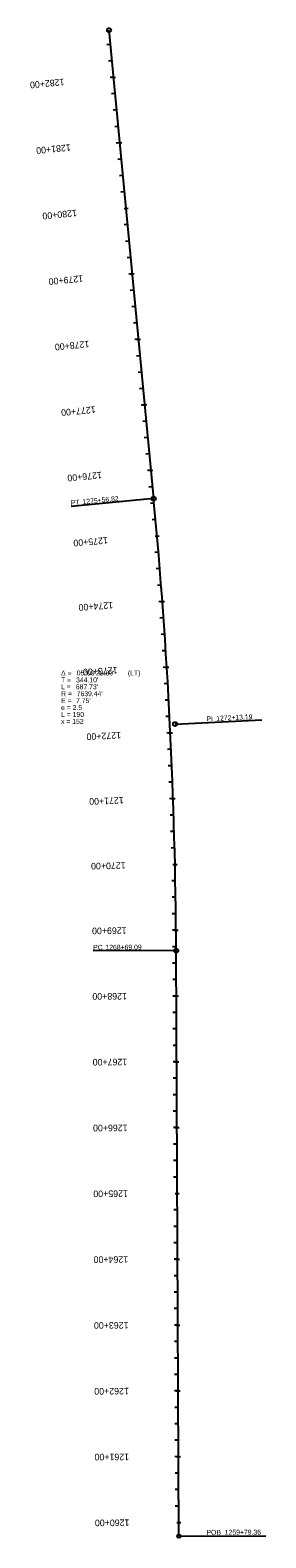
# Model space of a CAD drawing. Extents: x 19548215 to 19548727, y 7547983 to 7562114.
# Drawn here: x 19548369 to 19548727, y 7547983 to 7550274 of the extents above; entities that cross this region are included whole.
import ezdxf

# ---------------------------------------------------------------- set-up
doc = ezdxf.new("R2010")
doc.units = 0
for name, color, linetype in [('Contours Major', 7, 'Continuous'), ('Contours Minor', 7, 'Continuous'), ('Default', 7, 'Continuous'), ('TextAlignment', 7, 'Continuous'), ('TextAlignmentSml', 7, 'Continuous')]:
    doc.layers.add(name, color=color, linetype=linetype)

msp = doc.modelspace()

# ---------------------------------------------------------------- linework, layer by layer
at = {"layer": 'Contours Major'}
for p, q in [((19548495.4, 7550202), (19548490, 7550201.5)), ((19548504.9, 7550102.4), (19548499.5, 7550101.9)), ((19548511.3, 7550002.6), (19548517.4, 7550003.2)), ((19548523.8, 7549903.3), (19548518.4, 7549902.8)), ((19548533.3, 7549803.8), (19548527.8, 7549803.3)), ((19548542.7, 7549704.2), (19548537.3, 7549703.7)), ((19548552.2, 7549604.7), (19548546.8, 7549604.2)), ((19548558.4, 7549504.8), (19548564.5, 7549505.4)), ((19548569.5, 7549405.4), (19548564.1, 7549405)), ((19548576.3, 7549305.7), (19548570.8, 7549305.3)), ((19548581.7, 7549205.8), (19548576.3, 7549205.5)), ((19548585.9, 7549105.9), (19548580.4, 7549105.7)), ((19548585.6, 7549005.9), (19548591.8, 7549006)), ((19548590.2, 7548905.9), (19548584.8, 7548905.9)), ((19548590.8, 7548805.9), (19548585.3, 7548805.9)), ((19548591.2, 7548705.9), (19548585.8, 7548705.9)), ((19548591.7, 7548605.9), (19548586.2, 7548605.9)), ((19548589.1, 7548505.9), (19548595.2, 7548506)), ((19548592.6, 7548405.9), (19548587.2, 7548405.9)), ((19548593.1, 7548305.9), (19548587.7, 7548305.9)), ((19548593.6, 7548205.9), (19548588.1, 7548205.9)), ((19548594.1, 7548106), (19548588.6, 7548105.9)), ((19548591.5, 7548005.9), (19548597.6, 7548006))]:
    msp.add_line(p, q, dxfattribs=at)
at = {"layer": 'Contours Minor'}
for p, q in [((19548556.3, 7549561.7), (19548488.6, 7550273.5)), ((19548594.6, 7547985.3), (19548590.4, 7548875))]:
    msp.add_line(p, q, dxfattribs=at)
msp.add_arc((19540951.1, 7548839.1), 7639.4, 0.26937, 5.42737, dxfattribs=at)
at = {"layer": 'Default'}
msp.add_line((19548556.3, 7549561.7), (19548488.6, 7550273.5), dxfattribs=at)
msp.add_arc((19540951.1, 7548839.1), 7639.4, 0.26937, 5.42737, dxfattribs=at)
at = {"layer": 'TextAlignment'}
for p, q in [((19548556.3, 7549561.7), (19548430.8, 7549549.8)), ((19548430.8, 7549549.8), (19548430.8, 7549549.8)), ((19548588.8, 7549219.1), (19548720.7, 7549225.7)), ((19548720.7, 7549225.7), (19548720.7, 7549225.7)), ((19548590.4, 7548875), (19548464.4, 7548874.4)), ((19548464.4, 7548874.4), (19548464.4, 7548874.4)), ((19548594.6, 7547985.3), (19548726.6, 7547985.9)), ((19548726.6, 7547985.9), (19548726.6, 7547985.9))]:
    msp.add_line(p, q, dxfattribs=at)
for centre, radius in [((19548488.6, 7550273.5), 3.12), ((19548556.3, 7549561.7), 3.12), ((19548588.8, 7549219.1), 3.12), ((19548590.4, 7548875), 3.12), ((19548594.6, 7547985.3), 2.67)]:
    msp.add_circle(centre, radius, dxfattribs=at)
at = {"layer": 'TextAlignmentSml'}
for p, q in [((19548490.7, 7550251.8), (19548485.3, 7550251.2)), ((19548493.1, 7550226.9), (19548487.6, 7550226.3)), ((19548492.4, 7550201.7), (19548498.5, 7550202.3)), ((19548497.8, 7550177.1), (19548492.4, 7550176.6)), ((19548500.2, 7550152.2), (19548494.7, 7550151.7)), ((19548502.5, 7550127.3), (19548497.1, 7550126.8)), ((19548501.9, 7550102.1), (19548507.9, 7550102.7)), ((19548507.3, 7550077.5), (19548501.8, 7550077)), ((19548509.6, 7550052.6), (19548504.2, 7550052.1)), ((19548512, 7550027.8), (19548506.6, 7550027.2)), ((19548511.3, 7550002.6), (19548517.4, 7550003.2)), ((19548516.7, 7549978), (19548511.3, 7549977.5)), ((19548519.1, 7549953.1), (19548513.7, 7549952.6)), ((19548521.5, 7549928.2), (19548516, 7549927.7)), ((19548520.8, 7549903), (19548526.9, 7549903.6)), ((19548526.2, 7549878.4), (19548520.7, 7549877.9)), ((19548528.5, 7549853.5), (19548523.1, 7549853)), ((19548530.9, 7549828.7), (19548525.5, 7549828.1)), ((19548530.2, 7549803.5), (19548536.3, 7549804.1)), ((19548535.6, 7549778.9), (19548530.2, 7549778.4)), ((19548538, 7549754), (19548532.6, 7549753.5)), ((19548540.4, 7549729.1), (19548534.9, 7549728.6)), ((19548539.7, 7549703.9), (19548545.8, 7549704.5)), ((19548545.1, 7549679.3), (19548539.7, 7549678.8)), ((19548547.5, 7549654.4), (19548542, 7549653.9)), ((19548549.8, 7549629.6), (19548544.4, 7549629)), ((19548549.1, 7549604.4), (19548555.2, 7549605)), ((19548554.6, 7549579.8), (19548549.1, 7549579.3)), ((19548556.9, 7549554.9), (19548551.5, 7549554.4)), ((19548559.2, 7549530), (19548553.8, 7549529.5)), ((19548558.4, 7549504.8), (19548564.5, 7549505.4)), ((19548563.6, 7549480.2), (19548558.1, 7549479.7)), ((19548565.6, 7549455.3), (19548560.2, 7549454.8)), ((19548567.6, 7549430.4), (19548562.2, 7549429.9)), ((19548566.5, 7549405.2), (19548572.6, 7549405.6)), ((19548571.3, 7549380.5), (19548565.9, 7549380.1)), ((19548573, 7549355.5), (19548567.6, 7549355.2)), ((19548574.7, 7549330.6), (19548569.2, 7549330.3)), ((19548573.2, 7549305.5), (19548579.3, 7549305.8)), ((19548577.7, 7549280.7), (19548572.3, 7549280.4)), ((19548579.2, 7549255.7), (19548573.7, 7549255.4)), ((19548580.5, 7549230.8), (19548575, 7549230.5)), ((19548578.7, 7549205.7), (19548584.8, 7549205.9)), ((19548582.9, 7549180.8), (19548577.4, 7549180.6)), ((19548584, 7549155.9), (19548578.5, 7549155.6)), ((19548584.9, 7549130.9), (19548579.5, 7549130.7)), ((19548582.8, 7549105.8), (19548588.9, 7549106)), ((19548586.7, 7549080.9), (19548581.2, 7549080.7)), ((19548587.4, 7549055.9), (19548582, 7549055.8)), ((19548588.1, 7549030.9), (19548582.7, 7549030.8)), ((19548585.6, 7549005.9), (19548591.8, 7549006)), ((19548589.2, 7548980.9), (19548583.7, 7548980.8)), ((19548589.6, 7548955.9), (19548584.2, 7548955.9)), ((19548590, 7548930.9), (19548584.5, 7548930.9)), ((19548587.2, 7548905.9), (19548593.3, 7548906)), ((19548590.4, 7548880.9), (19548584.9, 7548880.9)), ((19548590.5, 7548855.9), (19548585.1, 7548855.9)), ((19548590.6, 7548830.9), (19548585.2, 7548830.9)), ((19548587.7, 7548805.9), (19548593.8, 7548806)), ((19548590.9, 7548780.9), (19548585.4, 7548780.9)), ((19548591, 7548755.9), (19548585.5, 7548755.9)), ((19548591.1, 7548730.9), (19548585.7, 7548730.9)), ((19548588.2, 7548705.9), (19548594.3, 7548706)), ((19548591.4, 7548680.9), (19548585.9, 7548680.9)), ((19548591.5, 7548655.9), (19548586, 7548655.9)), ((19548591.6, 7548630.9), (19548586.1, 7548630.9)), ((19548588.6, 7548605.9), (19548594.8, 7548606)), ((19548591.8, 7548580.9), (19548586.4, 7548580.9)), ((19548591.9, 7548555.9), (19548586.5, 7548555.9)), ((19548592.1, 7548530.9), (19548586.6, 7548530.9)), ((19548589.1, 7548505.9), (19548595.2, 7548506)), ((19548592.3, 7548480.9), (19548586.8, 7548480.9)), ((19548592.4, 7548455.9), (19548586.9, 7548455.9)), ((19548592.5, 7548430.9), (19548587.1, 7548430.9)), ((19548589.6, 7548405.9), (19548595.7, 7548406)), ((19548592.8, 7548380.9), (19548587.3, 7548380.9)), ((19548592.9, 7548355.9), (19548587.4, 7548355.9)), ((19548593, 7548330.9), (19548587.5, 7548330.9)), ((19548590.1, 7548305.9), (19548596.2, 7548306)), ((19548593.2, 7548280.9), (19548587.8, 7548280.9)), ((19548593.3, 7548255.9), (19548587.9, 7548255.9)), ((19548593.5, 7548230.9), (19548588, 7548230.9)), ((19548590.5, 7548205.9), (19548596.6, 7548206)), ((19548593.7, 7548180.9), (19548588.2, 7548180.9)), ((19548593.8, 7548156), (19548588.4, 7548155.9)), ((19548593.9, 7548131), (19548588.5, 7548130.9)), ((19548591, 7548105.9), (19548597.1, 7548106)), ((19548594.2, 7548081), (19548588.7, 7548080.9)), ((19548594.3, 7548056), (19548588.8, 7548055.9)), ((19548594.4, 7548031), (19548588.9, 7548030.9)), ((19548591.5, 7548005.9), (19548597.6, 7548006))]:
    msp.add_line(p, q, dxfattribs=at)

# ---------------------------------------------------------------- texts
at = {"layer": 'Contours Major'}
for s, rotation, p in [('1280+00', 185.4274, (19548439.2, 7550000.8)), ('1275+00', 185.0012, (19548486.3, 7549503.5)), ('1270+00', 181.2512, (19548513.6, 7549009.3)), ('1265+00', 180.2694, (19548517.2, 7548510.6)), ('1260+00', 180.2694, (19548519.5, 7548010.6))]:
    msp.add_text(s, height=10.02, rotation=rotation, dxfattribs=at).set_placement(p)
at = {"layer": 'TextAlignment'}
for s, rotation, p in [('1275+56.82', 5.4274, (19548448.7, 7549553.1)), ('PT', 5.4274, (19548430.7, 7549551.4)), ('PI ', 2.8484, (19548636.6, 7549223.2)), ('1272+13.19', 2.8484, (19548651.5, 7549223.9)), ('PC', 0.2694, (19548464.4, 7548876.1)), ('1268+69.09', 0.2694, (19548483.1, 7548876.2)), ('POB ', 0.2694, (19548636.6, 7547987.2)), ('1259+79.36', 0.2694, (19548664.3, 7547987.3))]:
    msp.add_text(s, height=7.5, rotation=rotation, dxfattribs=at).set_placement(p)
for s, p in [('T = ', (19548415.7, 7549282.5)), ('Δ = ', (19548415.7, 7549293)), ("344.10'", (19548438.5, 7549282.5)), ('05°09\'28.80"', (19548439.5, 7549293)), (' (LT)', (19548514.3, 7549293)), ('L = ', (19548415.7, 7549272)), ('R = ', (19548415.7, 7549261.5)), ("687.73'", (19548438.1, 7549272)), ("7639.44'", (19548439.4, 7549261.5)), ('e = 2.5', (19548415.7, 7549240.5)), ('E = ', (19548415.7, 7549251)), ("7.75'", (19548438.5, 7549251)), ('x = 152', (19548415.7, 7549219.5)), ('L = 190', (19548415.7, 7549230))]:
    msp.add_text(s, height=7.5, dxfattribs=at).set_placement(p)
at = {"layer": 'TextAlignmentSml'}
for s, rotation, p in [('1282+00', 185.4274, (19548420.3, 7550199.9)), ('1281+00', 185.4274, (19548429.8, 7550100.3)), ('1280+00', 185.4274, (19548439.2, 7550000.8)), ('1279+00', 185.4274, (19548448.7, 7549901.2)), ('1278+00', 185.4274, (19548458.1, 7549801.7)), ('1277+00', 185.4274, (19548467.6, 7549702.1)), ('1276+00', 185.4274, (19548477.1, 7549602.6)), ('1275+00', 185.0012, (19548486.3, 7549503.5)), ('1274+00', 184.2512, (19548494.3, 7549404.9)), ('1273+00', 183.5012, (19548501.1, 7549306.1)), ('1272+00', 182.7512, (19548506.6, 7549207.2)), ('1271+00', 182.0012, (19548510.7, 7549108.3)), ('1270+00', 181.2512, (19548513.6, 7549009.3)), ('1269+00', 180.5012, (19548515.2, 7548910.3)), ('1268+00', 180.2694, (19548515.7, 7548810.6)), ('1267+00', 180.2694, (19548516.2, 7548710.6)), ('1266+00', 180.2694, (19548516.7, 7548610.6)), ('1265+00', 180.2694, (19548517.2, 7548510.6)), ('1264+00', 180.2694, (19548517.6, 7548410.6)), ('1263+00', 180.2694, (19548518.1, 7548310.6)), ('1262+00', 180.2694, (19548518.6, 7548210.6)), ('1261+00', 180.2694, (19548519, 7548110.6)), ('1260+00', 180.2694, (19548519.5, 7548010.6))]:
    msp.add_text(s, height=10.02, rotation=rotation, dxfattribs=at).set_placement(p)

doc.saveas('drawing.dxf')
